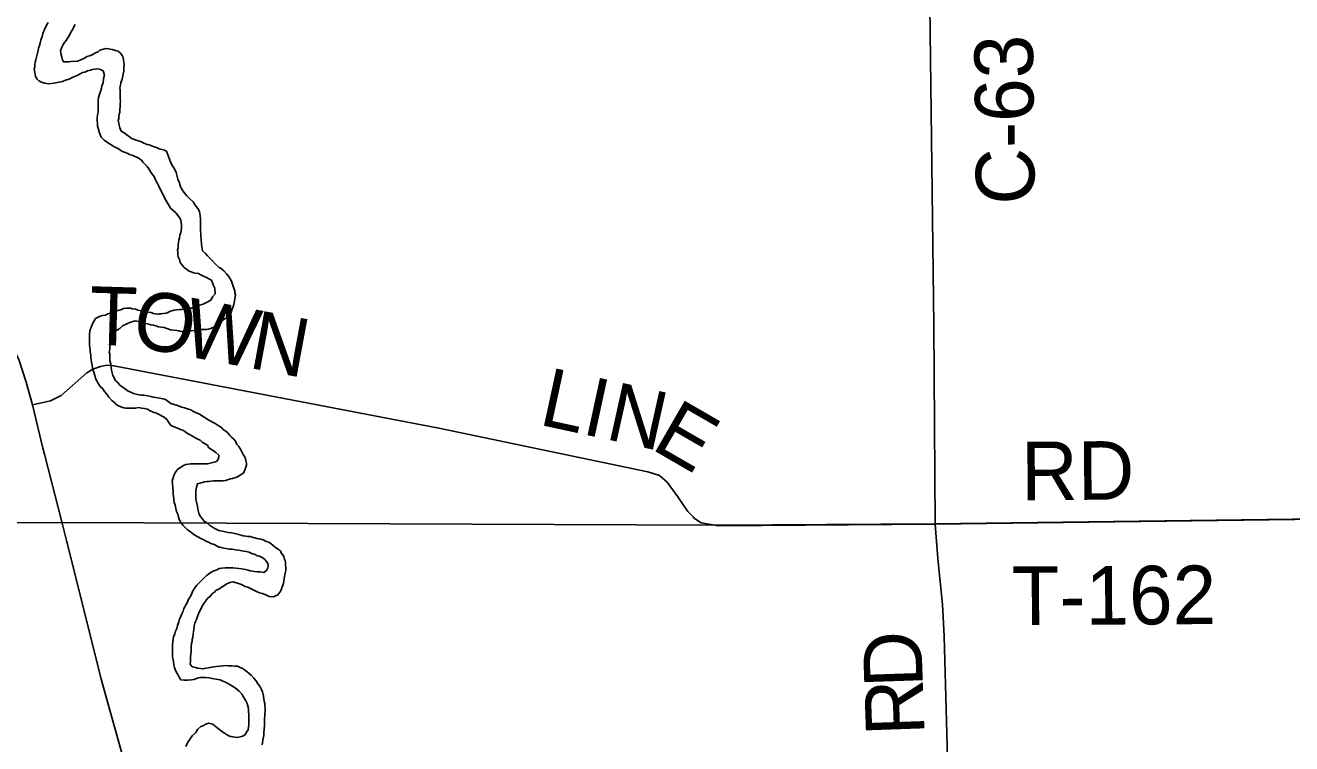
# Model space of a CAD drawing. Extents: x 0 to 34, y 0 to 22.
# Drawn here: x 5.159 to 6.388, y 15.155 to 15.852 of the extents above; entities that cross this region are included whole.
import ezdxf

# ---------------------------------------------------------------- set-up
doc = ezdxf.new("R2010")
doc.units = 0
for name, color, linetype in [('GM_X_Corporation', 7, 'Continuous'), ('GM_X_County_Road', 7, 'Continuous'), ('GM_X_County_Road_Text', 7, 'Continuous'), ('GM_X_Minor_River', 7, 'Continuous'), ('GM_X_Township_Road', 7, 'Continuous'), ('GM_X_Township_Road_Text', 7, 'Continuous')]:
    doc.layers.add(name, color=color, linetype=linetype)

msp = doc.modelspace()

# ---------------------------------------------------------------- linework, layer by layer
at = {"layer": 'GM_X_Corporation'}
msp.add_lwpolyline([(2.1, 20.3879), (2.1, 15.3574), (2.6127, 15.3592), (3.4135, 15.3624), (4.1534, 15.3654), (4.1554, 15.3654), (5.1944, 15.3696), (5.8313, 15.3671), (6.0415, 15.3685), (7.1072, 15.3824), (7.0838, 16.6084)], dxfattribs=at)
msp.add_lwpolyline([(2.1, 15.3574), (2.1, 14.1), (7.1335, 14.1), (7.1269, 14.4049), (7.1267, 14.4123), (7.1215, 14.6514), (7.118, 14.8105), (7.1072, 15.3824), (6.0415, 15.3685), (5.8313, 15.3671), (5.1944, 15.3696), (4.1554, 15.3654), (4.1534, 15.3654), (3.4135, 15.3624), (2.6127, 15.3592)], close=True, dxfattribs=at)
at = {"layer": 'GM_X_County_Road'}
for points in [[(6.0417, 15.3679), (6.0405, 15.5612), (6.0354, 15.9744), (6.0304, 16.3839), (6.0288, 16.6057), (6.0226, 16.9752), (6.0207, 17.2272)], [(6.1825, 14.1), (6.1814, 14.103), (6.0754, 14.3845), (6.0658, 14.624), (6.0555, 15.0705), (6.0505, 15.2593), (6.0489, 15.2901), (6.0444, 15.3349), (6.0417, 15.3679)]]:
    msp.add_lwpolyline(points, dxfattribs=at)
at = {"layer": 'GM_X_Minor_River'}
for points in [[(5.1812, 15.8546), (5.1792, 15.8513), (5.1777, 15.8478), (5.1761, 15.8441), (5.1753, 15.841), (5.1741, 15.8376), (5.1733, 15.8346), (5.1726, 15.8323), (5.1718, 15.8297), (5.1714, 15.8274), (5.1705, 15.8236), (5.1698, 15.821), (5.169, 15.8183), (5.1686, 15.816), (5.1681, 15.8137), (5.1681, 15.8115), (5.1677, 15.8092), (5.1681, 15.8065), (5.1684, 15.8046), (5.1688, 15.8023), (5.1703, 15.7997), (5.1721, 15.7981), (5.1748, 15.7966), (5.1778, 15.7958), (5.1797, 15.7954), (5.1816, 15.795), (5.1839, 15.7953), (5.1866, 15.7957), (5.19, 15.7964), (5.1949, 15.7975), (5.198, 15.7986), (5.2014, 15.7997), (5.2037, 15.8008), (5.2098, 15.8034), (5.2121, 15.8049), (5.2144, 15.806), (5.2167, 15.8063), (5.2194, 15.8078), (5.2221, 15.8085), (5.224, 15.8089), (5.2263, 15.8093), (5.2282, 15.8096), (5.2308, 15.8092), (5.2327, 15.8088), (5.2346, 15.8076), (5.2357, 15.8034), (5.2349, 15.8004), (5.2345, 15.7962), (5.2333, 15.7932), (5.2329, 15.7909), (5.2321, 15.7887), (5.2313, 15.786), (5.2305, 15.7837), (5.2301, 15.7818), (5.2297, 15.7788), (5.2297, 15.7769), (5.2296, 15.7746), (5.2296, 15.7723), (5.2296, 15.7697), (5.2296, 15.7678), (5.2291, 15.7651), (5.2287, 15.7617), (5.2287, 15.7598), (5.229, 15.756), (5.229, 15.7541), (5.2312, 15.7465), (5.2327, 15.7434), (5.2353, 15.7404), (5.2376, 15.7388), (5.2413, 15.7365), (5.244, 15.7349), (5.2459, 15.7338), (5.2485, 15.7326), (5.2508, 15.731), (5.2534, 15.7295), (5.2553, 15.7287), (5.2583, 15.7275), (5.2602, 15.7267), (5.2625, 15.726), (5.2663, 15.7244), (5.2686, 15.7232), (5.272, 15.7209)], [(5.2997, 15.7194), (5.296, 15.7297), (5.2941, 15.7309), (5.2915, 15.7313), (5.2888, 15.7321), (5.2862, 15.7333), (5.2839, 15.7341), (5.279, 15.736), (5.2771, 15.7364), (5.2741, 15.7376), (5.2722, 15.7384), (5.2699, 15.7396), (5.2676, 15.7403), (5.265, 15.7411), (5.2627, 15.7419), (5.2597, 15.7442), (5.2578, 15.7454), (5.2548, 15.7477), (5.2521, 15.7493), (5.2507, 15.7523), (5.2499, 15.755), (5.2496, 15.7569), (5.2492, 15.7596), (5.2496, 15.7615), (5.2497, 15.7634), (5.2501, 15.7656), (5.2505, 15.7675), (5.2505, 15.7698), (5.2509, 15.7736), (5.2509, 15.7755), (5.2514, 15.7786), (5.251, 15.7805), (5.251, 15.7843), (5.2511, 15.7865), (5.2511, 15.7892), (5.2507, 15.7911), (5.2512, 15.7938), (5.2516, 15.796), (5.2528, 15.7998), (5.2539, 15.8044), (5.2544, 15.8074), (5.2544, 15.8104), (5.2548, 15.8139), (5.2545, 15.8158), (5.2541, 15.8184), (5.2538, 15.8207), (5.253, 15.8226), (5.2512, 15.8249), (5.2489, 15.8269), (5.2466, 15.8276), (5.2432, 15.8284), (5.2413, 15.8288), (5.2394, 15.8292), (5.2371, 15.8293), (5.2349, 15.8289), (5.2314, 15.8278), (5.2295, 15.8263), (5.2272, 15.8252), (5.2238, 15.8234), (5.2211, 15.8222), (5.2188, 15.8215), (5.2165, 15.82), (5.2123, 15.8182), (5.2096, 15.8171), (5.2035, 15.8167), (5.2013, 15.8164), (5.1978, 15.8164), (5.1959, 15.8165), (5.1948, 15.8191), (5.1945, 15.821), (5.1934, 15.8245), (5.193, 15.8271), (5.1946, 15.8313), (5.1958, 15.8332), (5.1969, 15.8351), (5.1985, 15.837), (5.1996, 15.8388), (5.2008, 15.8407), (5.202, 15.843), (5.2031, 15.8453), (5.2047, 15.8475), (5.2058, 15.8498), (5.2074, 15.8528)], [(5.272, 15.7209), (5.2731, 15.719), (5.2757, 15.7167), (5.2772, 15.7148), (5.2787, 15.7128), (5.2802, 15.7105), (5.2821, 15.7075), (5.2839, 15.7052), (5.2854, 15.7021), (5.2861, 15.7002), (5.2873, 15.6983), (5.2884, 15.696), (5.2891, 15.6941), (5.291, 15.6907), (5.2921, 15.6884), (5.2932, 15.6864), (5.2939, 15.6845), (5.2998, 15.6744)], [(5.2999, 15.5566), (5.3059, 15.5558), (5.3078, 15.5554), (5.3101, 15.555), (5.312, 15.555), (5.3146, 15.5553), (5.3173, 15.5557), (5.32, 15.5557), (5.3223, 15.556), (5.3242, 15.5564), (5.3261, 15.5564), (5.3287, 15.5567), (5.3322, 15.5567), (5.3348, 15.5567), (5.3367, 15.5571), (5.339, 15.5578), (5.3432, 15.5597), (5.3471, 15.5619), (5.352, 15.5669), (5.3574, 15.5702), (5.3605, 15.579), (5.3612, 15.5812), (5.362, 15.5843), (5.3624, 15.5873), (5.3628, 15.5904), (5.3624, 15.5923), (5.3621, 15.5942), (5.3617, 15.5961), (5.361, 15.598), (5.3598, 15.6018), (5.3591, 15.6037), (5.3576, 15.606), (5.3561, 15.6087), (5.3542, 15.611), (5.3515, 15.6136), (5.3489, 15.6159), (5.347, 15.6171), (5.3435, 15.6202), (5.3405, 15.6236), (5.3379, 15.6259), (5.3356, 15.6282), (5.3337, 15.6305), (5.331, 15.6332), (5.3303, 15.637), (5.3296, 15.6431), (5.3289, 15.6534), (5.3289, 15.6553), (5.3289, 15.6572), (5.3289, 15.6591), (5.3289, 15.6613), (5.3289, 15.664), (5.3286, 15.667), (5.3282, 15.6693), (5.3278, 15.6712), (5.3263, 15.6743), (5.3237, 15.6774), (5.3218, 15.6808), (5.3187, 15.6835), (5.3157, 15.6865), (5.3142, 15.6884), (5.3119, 15.6915), (5.31, 15.6946), (5.3089, 15.6976), (5.3082, 15.6999), (5.307, 15.7026), (5.3063, 15.7052), (5.3052, 15.709), (5.3048, 15.7109), (5.3029, 15.7136), (5.301, 15.7167), (5.2997, 15.7194)], [(5.2998, 15.6744), (5.305, 15.6699), (5.3072, 15.6672), (5.3095, 15.6638), (5.3102, 15.6611), (5.3106, 15.658), (5.3106, 15.6561), (5.3102, 15.6527), (5.3098, 15.6508), (5.309, 15.6482), (5.3086, 15.6459), (5.3079, 15.6436), (5.3075, 15.6413), (5.3071, 15.6387), (5.3071, 15.636), (5.3067, 15.6341), (5.307, 15.6318), (5.307, 15.6299), (5.3074, 15.6273), (5.3085, 15.6246), (5.3093, 15.6219), (5.3112, 15.6192), (5.3131, 15.6169), (5.3153, 15.6154), (5.3172, 15.6139), (5.3199, 15.6127), (5.3222, 15.6119), (5.3241, 15.6115), (5.3271, 15.6111), (5.3294, 15.61), (5.3317, 15.6085), (5.3347, 15.6073), (5.337, 15.6061), (5.3397, 15.6046), (5.3415, 15.5996), (5.3427, 15.597), (5.343, 15.5913), (5.3407, 15.5886), (5.3392, 15.5856), (5.3361, 15.5837), (5.3342, 15.5826), (5.3323, 15.5818), (5.3304, 15.5811), (5.3281, 15.5803), (5.3258, 15.5792), (5.3231, 15.5785), (5.3208, 15.5777), (5.3189, 15.5774), (5.3155, 15.5766), (5.3132, 15.5766), (5.3109, 15.5763), (5.309, 15.5763), (5.3056, 15.5759), (5.3033, 15.5756), (5.2999, 15.5747)], [(5.2999, 15.5747), (5.296, 15.5728), (5.2926, 15.5724), (5.2907, 15.5721), (5.2888, 15.5721), (5.2869, 15.5717), (5.2831, 15.5725), (5.2812, 15.5733), (5.2785, 15.5737), (5.2763, 15.5741), (5.2732, 15.5749), (5.2713, 15.575), (5.2683, 15.5757), (5.266, 15.5765), (5.263, 15.5769), (5.2611, 15.5774), (5.2573, 15.5774), (5.2543, 15.5771), (5.2516, 15.5759), (5.2497, 15.5756), (5.247, 15.5745), (5.2443, 15.5738), (5.2417, 15.5726), (5.239, 15.5719), (5.2367, 15.5708), (5.234, 15.5705), (5.2317, 15.5697), (5.2291, 15.5686), (5.2271, 15.5675), (5.2244, 15.563), (5.2236, 15.5607), (5.2217, 15.5554), (5.2213, 15.552), (5.2212, 15.5489), (5.2212, 15.5467), (5.2212, 15.5436), (5.2211, 15.5413), (5.2215, 15.5394), (5.2218, 15.5375), (5.2218, 15.5356), (5.2222, 15.5337), (5.2225, 15.5318), (5.2225, 15.5295), (5.2229, 15.5276), (5.2232, 15.5253), (5.2236, 15.5234), (5.2243, 15.5204), (5.2246, 15.5177), (5.2254, 15.5154), (5.2261, 15.5131), (5.2268, 15.5112), (5.2272, 15.5093), (5.2283, 15.507), (5.2294, 15.5051), (5.2317, 15.5017), (5.2343, 15.4994), (5.2358, 15.4967), (5.238, 15.494), (5.2399, 15.4913), (5.2429, 15.4879), (5.2452, 15.4863), (5.2467, 15.4844), (5.2493, 15.4828), (5.2516, 15.4817), (5.2546, 15.4809), (5.2565, 15.4805), (5.263, 15.4804), (5.2656, 15.4804), (5.2691, 15.4811), (5.2717, 15.4807), (5.2744, 15.4803), (5.2774, 15.4795), (5.28, 15.4779), (5.2831, 15.4767), (5.2861, 15.4756), (5.2887, 15.4744), (5.2918, 15.4728), (5.2937, 15.4717), (5.2963, 15.4697), (5.3, 15.4639)], [(5.3, 15.4851), (5.295, 15.4888), (5.2927, 15.4895), (5.2908, 15.49), (5.2855, 15.4908), (5.2829, 15.4912), (5.2806, 15.492), (5.2779, 15.4924), (5.276, 15.4928), (5.2738, 15.4932), (5.2715, 15.4932), (5.2692, 15.4936), (5.2666, 15.494), (5.2639, 15.4948), (5.2613, 15.496), (5.2586, 15.4972), (5.256, 15.4991), (5.2537, 15.501), (5.2511, 15.5026), (5.2485, 15.5057), (5.2466, 15.5072), (5.2451, 15.5099), (5.244, 15.5122), (5.2432, 15.5148), (5.2425, 15.5175), (5.2422, 15.5202), (5.2418, 15.5232), (5.2411, 15.5267), (5.2408, 15.5301), (5.2408, 15.5331), (5.2404, 15.535), (5.2408, 15.5373), (5.2409, 15.5403), (5.2417, 15.5434), (5.2425, 15.5464), (5.2437, 15.5494), (5.2452, 15.5525), (5.2464, 15.5547), (5.2483, 15.5566), (5.2506, 15.5577), (5.2533, 15.5603), (5.256, 15.5618), (5.2586, 15.5629), (5.2613, 15.564), (5.2655, 15.5651), (5.2704, 15.5643), (5.2727, 15.5639), (5.2757, 15.5627), (5.2788, 15.5619), (5.2807, 15.5615), (5.2833, 15.5611), (5.2856, 15.5603), (5.2883, 15.5595), (5.2909, 15.5591), (5.2936, 15.5587), (5.2999, 15.5566)], [(5.4017, 15.2984), (5.404, 15.2995), (5.407, 15.3033), (5.4094, 15.3109), (5.4097, 15.3128), (5.4101, 15.3154), (5.4109, 15.3189), (5.4117, 15.3234), (5.4114, 15.331), (5.411, 15.3329), (5.4102, 15.3348), (5.4099, 15.3367), (5.4072, 15.3402), (5.4065, 15.3421), (5.4046, 15.3436), (5.4015, 15.3459), (5.3974, 15.349), (5.3951, 15.3505), (5.3928, 15.3513), (5.3898, 15.3529), (5.3875, 15.3536), (5.3837, 15.354), (5.3818, 15.3548), (5.3799, 15.3552), (5.3772, 15.356), (5.3749, 15.356), (5.373, 15.3564), (5.3704, 15.3568), (5.3662, 15.358), (5.3624, 15.3591), (5.3593, 15.3595), (5.3559, 15.3599), (5.3529, 15.3607), (5.3487, 15.3615), (5.3468, 15.3619), (5.3422, 15.3642), (5.3403, 15.3654), (5.338, 15.3669), (5.3346, 15.3696), (5.3327, 15.3707), (5.3301, 15.3738), (5.3286, 15.3757), (5.3274, 15.3788), (5.3267, 15.3814), (5.3263, 15.3833), (5.3256, 15.3868), (5.3248, 15.3906), (5.3245, 15.3932), (5.3245, 15.3967), (5.3245, 15.3986), (5.3245, 15.4005), (5.3249, 15.4039), (5.3261, 15.4073), (5.3283, 15.4077), (5.3329, 15.4091), (5.3352, 15.4095), (5.3371, 15.4095), (5.339, 15.4099), (5.3417, 15.4102), (5.3436, 15.4102), (5.3466, 15.4102), (5.3508, 15.4102), (5.3531, 15.4105), (5.3581, 15.412), (5.36, 15.4124), (5.3642, 15.4135), (5.3691, 15.4165), (5.3711, 15.418), (5.373, 15.4233), (5.3734, 15.4252), (5.3734, 15.4271), (5.373, 15.4298), (5.3723, 15.4328), (5.3704, 15.4355), (5.3689, 15.4382), (5.3677, 15.4409), (5.3662, 15.4435), (5.3643, 15.4454), (5.3628, 15.4485), (5.3613, 15.4504), (5.359, 15.4523), (5.3575, 15.4542), (5.3553, 15.4565), (5.3534, 15.4581), (5.3511, 15.4596), (5.3492, 15.4619), (5.3462, 15.4638), (5.3431, 15.4657), (5.337, 15.4688), (5.3325, 15.4719), (5.3279, 15.4746), (5.3241, 15.4765), (5.3215, 15.4777), (5.3196, 15.4788), (5.3173, 15.4796), (5.3135, 15.4808), (5.3108, 15.4816), (5.3066, 15.4831), (5.3, 15.4851)], [(5.3, 15.4639), (5.3061, 15.4614), (5.3096, 15.4599), (5.3118, 15.4591), (5.3137, 15.458), (5.3164, 15.456), (5.3194, 15.4545), (5.3217, 15.453), (5.3236, 15.4518), (5.3263, 15.4506), (5.3286, 15.4495), (5.3305, 15.4476), (5.3335, 15.446), (5.3362, 15.4445), (5.3365, 15.4426), (5.3388, 15.4407), (5.3411, 15.4395), (5.3437, 15.4376), (5.3468, 15.4349), (5.3464, 15.4315), (5.3444, 15.4288), (5.3422, 15.4281), (5.3395, 15.4274), (5.3357, 15.4266), (5.3334, 15.4266), (5.3311, 15.4267), (5.3288, 15.4267), (5.3269, 15.4267), (5.3246, 15.4267), (5.3223, 15.4267), (5.3193, 15.4267), (5.3174, 15.4264), (5.3147, 15.426), (5.3124, 15.4249), (5.3098, 15.4234), (5.3067, 15.4211), (5.3048, 15.4185), (5.3032, 15.4154), (5.3013, 15.4097), (5.3017, 15.4075), (5.302, 15.4033), (5.3024, 15.3998), (5.3024, 15.3972), (5.3027, 15.3949), (5.3031, 15.3919), (5.3035, 15.3892), (5.3042, 15.3869), (5.305, 15.3831), (5.3057, 15.3804), (5.3068, 15.3778), (5.3076, 15.3747), (5.3087, 15.372), (5.3102, 15.3694), (5.3117, 15.3671), (5.3144, 15.3644), (5.3163, 15.3625), (5.319, 15.3609), (5.3212, 15.359), (5.3235, 15.3575), (5.3265, 15.3559), (5.3292, 15.354), (5.3322, 15.3529), (5.3341, 15.3517), (5.336, 15.3509), (5.3391, 15.3494), (5.3421, 15.3482), (5.3452, 15.3467), (5.3471, 15.3459), (5.349, 15.3455), (5.3516, 15.3447), (5.3539, 15.3443), (5.3566, 15.3439), (5.3596, 15.3439), (5.363, 15.3431), (5.3661, 15.3427), (5.3707, 15.342), (5.3733, 15.3416), (5.376, 15.3408), (5.3779, 15.34), (5.3798, 15.3392), (5.3821, 15.3385), (5.384, 15.3373), (5.3863, 15.3369), (5.3893, 15.3354), (5.3912, 15.3338), (5.3931, 15.3319), (5.3942, 15.33), (5.3946, 15.3277), (5.3942, 15.3258), (5.393, 15.3232), (5.3904, 15.3213), (5.3869, 15.3217), (5.3839, 15.3217), (5.3812, 15.3221), (5.3793, 15.3225), (5.377, 15.3229), (5.3751, 15.3233), (5.3725, 15.3241)], [(5.3725, 15.3241), (5.369, 15.3248), (5.3603, 15.3257), (5.3572, 15.3257), (5.3546, 15.3257), (5.3527, 15.3257), (5.3496, 15.3254), (5.347, 15.325), (5.3447, 15.3239), (5.3412, 15.3224), (5.3389, 15.3212), (5.3366, 15.3197), (5.3347, 15.3182), (5.3317, 15.3152), (5.3286, 15.3122), (5.3267, 15.3103), (5.3252, 15.3084), (5.3228, 15.3054), (5.3213, 15.3027), (5.3198, 15.2993), (5.3182, 15.2967), (5.3171, 15.2948), (5.3159, 15.2917), (5.3148, 15.2898), (5.3136, 15.2879), (5.3128, 15.2861), (5.3121, 15.2838), (5.3109, 15.2811), (5.3098, 15.2785), (5.3086, 15.2762), (5.3078, 15.2732), (5.3067, 15.2697), (5.3059, 15.2667), (5.3047, 15.2644), (5.304, 15.2618), (5.3028, 15.2587), (5.3024, 15.2568), (5.302, 15.2534), (5.3016, 15.2515), (5.3016, 15.247), (5.3016, 15.2435), (5.3019, 15.2393), (5.3023, 15.2367), (5.3027, 15.2344), (5.303, 15.2317), (5.3038, 15.2291), (5.3045, 15.2272), (5.3053, 15.2249), (5.3068, 15.2222), (5.3083, 15.2195), (5.3098, 15.2172), (5.3132, 15.2168), (5.3167, 15.2168), (5.3201, 15.2172), (5.3224, 15.2175), (5.3243, 15.2179), (5.3266, 15.219), (5.3289, 15.2194), (5.3315, 15.2194), (5.3342, 15.2194), (5.3373, 15.219), (5.3418, 15.2182), (5.3441, 15.2178), (5.346, 15.2174), (5.3479, 15.217), (5.3498, 15.2162), (5.3532, 15.2147), (5.3555, 15.2135), (5.3582, 15.212), (5.3608, 15.2104), (5.3627, 15.2093), (5.3646, 15.2077), (5.3665, 15.2062), (5.3695, 15.2028), (5.3703, 15.2009), (5.3726, 15.1974), (5.3741, 15.194), (5.3752, 15.1906), (5.3756, 15.1883), (5.3756, 15.1856), (5.3759, 15.1837), (5.3759, 15.1803), (5.3759, 15.178), (5.3759, 15.1761), (5.3759, 15.1734), (5.3751, 15.1685), (5.3735, 15.1662), (5.3724, 15.1639), (5.3705, 15.1628), (5.3686, 15.1621), (5.3648, 15.1613), (5.3625, 15.1614), (5.3602, 15.1617), (5.3583, 15.1621), (5.3564, 15.1629), (5.3541, 15.1641), (5.3522, 15.1652), (5.3496, 15.1671), (5.3461, 15.1698), (5.3431, 15.1721), (5.3408, 15.174)], [(5.3887, 15.1539), (5.3891, 15.1558), (5.3895, 15.1589), (5.3903, 15.1631), (5.3903, 15.1653), (5.3907, 15.1695), (5.3911, 15.1726), (5.3911, 15.1752), (5.3911, 15.1779), (5.3911, 15.1798), (5.3915, 15.1817), (5.3915, 15.184), (5.3916, 15.1866), (5.3916, 15.1893), (5.3912, 15.192), (5.3912, 15.1942), (5.3908, 15.1965), (5.3905, 15.1984), (5.3901, 15.2011), (5.3897, 15.203), (5.389, 15.2053), (5.3882, 15.2076), (5.3864, 15.211), (5.3848, 15.2129), (5.3826, 15.2164), (5.3807, 15.2187), (5.378, 15.2217), (5.3742, 15.2248), (5.3716, 15.2267), (5.3697, 15.2282), (5.3674, 15.229), (5.3647, 15.2302), (5.3621, 15.2302), (5.3594, 15.2306), (5.356, 15.2306), (5.3537, 15.231), (5.351, 15.2306), (5.3476, 15.2303), (5.3445, 15.2299), (5.3415, 15.2296), (5.3327, 15.2281), (5.3308, 15.2277), (5.3289, 15.2281), (5.3259, 15.2285), (5.324, 15.2289), (5.3209, 15.2297), (5.319, 15.2324), (5.3191, 15.235), (5.3191, 15.2373), (5.3191, 15.2396), (5.3195, 15.2419), (5.3199, 15.2442), (5.3199, 15.2465), (5.3199, 15.2491), (5.3203, 15.2525), (5.3207, 15.2544), (5.3207, 15.2563), (5.3215, 15.2586), (5.3219, 15.2617), (5.3226, 15.2655), (5.3227, 15.2696), (5.3234, 15.2719), (5.3242, 15.2738), (5.325, 15.2757), (5.3265, 15.2795), (5.3281, 15.2833), (5.3315, 15.2901), (5.3338, 15.2935), (5.3358, 15.2958), (5.3384, 15.2981), (5.3407, 15.3007), (5.3426, 15.3022), (5.3442, 15.3041), (5.3461, 15.3048), (5.3495, 15.3071), (5.3537, 15.3097), (5.3575, 15.3116), (5.3606, 15.312), (5.3625, 15.3116), (5.3659, 15.3104), (5.3686, 15.3096), (5.3724, 15.3077), (5.375, 15.3069), (5.3781, 15.3054), (5.38, 15.3042), (5.3834, 15.3027), (5.3861, 15.3015), (5.3891, 15.3008), (5.3929, 15.2992), (5.3956, 15.298), (5.3998, 15.2976), (5.4017, 15.2984)], [(5.3408, 15.174), (5.337, 15.1752), (5.3347, 15.1745), (5.3313, 15.1726), (5.3294, 15.1718), (5.3263, 15.1692), (5.324, 15.1658), (5.321, 15.1628), (5.3183, 15.159), (5.3164, 15.156), (5.3148, 15.1525)]]:
    msp.add_lwpolyline(points, dxfattribs=at)
at = {"layer": 'GM_X_Township_Road'}
msp.add_line((6.0417, 15.3679), (7.1074, 15.3818), dxfattribs=at)
for points in [[(5.1993, 15.351), (5.1946, 15.3691), (5.1775, 15.4359), (5.1761, 15.4416), (5.166, 15.4838), (5.1597, 15.5059), (5.153, 15.5268), (5.141, 15.5523), (5.1304, 15.5713), (5.1146, 15.5965), (5.0401, 15.707), (4.958, 15.827), (4.8429, 15.9965), (4.8301, 16.017), (4.8278, 16.0224)], [(5.166, 15.4838), (5.1834, 15.4877), (5.1936, 15.493), (5.2187, 15.5149), (5.2245, 15.5185), (5.232, 15.521), (5.2385, 15.5221), (5.2449, 15.5217), (5.5602, 15.4612), (5.7628, 15.4189), (5.7742, 15.4151), (5.7818, 15.4087), (5.792, 15.3946), (5.8019, 15.3802), (5.8069, 15.3752)], [(5.8069, 15.3752), (5.8083, 15.3737), (5.8148, 15.3692), (5.8315, 15.3665), (6.0417, 15.3679)], [(5.4657, 14.4522), (5.444, 14.4982), (5.3768, 14.6406), (5.3662, 14.6665), (5.3567, 14.6942), (5.346, 14.758), (5.3327, 14.8499), (5.3304, 14.8609), (5.3194, 14.8997), (5.2624, 15.1112), (5.2326, 15.2177), (5.1995, 15.35), (5.1993, 15.351)]]:
    msp.add_lwpolyline(points, dxfattribs=at)

# ---------------------------------------------------------------- texts
at = {"layer": 'GM_X_County_Road_Text'}
for s, height, rotation, p in [('C-63', 0.05682, 90.6858, (6.1384, 15.6783)), ('D', 0.0568, 91.931, (6.0299, 15.2105)), ('R', 0.0568, 92.0066, (6.0315, 15.1638))]:
    msp.add_text(s, height=height, rotation=rotation, dxfattribs=at).set_placement(p)
at = {"layer": 'GM_X_Township_Road_Text'}
for s, height, rotation, p in [('T', 0.0568, 358.2727, (5.2203, 15.5421)), ('O', 0.0568, 349.516, (5.2605, 15.5411)), ('W', 0.0568, 349.4714, (5.3096, 15.532)), ('N', 0.0568, 349.4716, (5.3744, 15.5199)), ('L', 0.0568, 347.7873, (5.6561, 15.4648)), ('I', 0.0568, 347.7777, (5.6976, 15.4558)), ('N', 0.0568, 347.4341, (5.7204, 15.4509)), ('E', 0.0568, 329.9867, (5.7649, 15.4417)), ('RD', 0.05682, 0.4937, (6.1254, 15.3911)), ('T-162', 0.05682, 0.2807, (6.116, 15.2702))]:
    msp.add_text(s, height=height, rotation=rotation, dxfattribs=at).set_placement(p)

doc.saveas('drawing.dxf')
